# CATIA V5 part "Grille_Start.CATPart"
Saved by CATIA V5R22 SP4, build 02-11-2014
Part number: Grille
Bounding box of the stored display mesh (mm): x 0 to 0, y -310 to 310, z 0 to 410
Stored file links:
  C:\DATA\Car_ASSY\教育モデル\4_SUR\Grille_Start.CATPart
  C:\DATA\Car_ASSY\教育モデル\4_SUR\Grille_FIN.CATPart
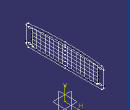
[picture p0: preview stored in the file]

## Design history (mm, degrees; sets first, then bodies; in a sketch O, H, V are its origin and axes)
Set1 "Boss_Danmen"
  Sketch1 on Plane1, origin (-185, 0, 0), H (0, 1, 0), V (0, 0, 1)
    circle A1 centre (-280, 370) radius 6
    circle A2 centre (-280, 260) radius 6
    circle A3 centre (280, 370) radius 6
    circle A4 centre (280, 260) radius 6
    circle A5 centre (-280, 370) radius 9
    point P1 (-280, 370)
    circle A6 centre (-280, 260) radius 9
    point P2 (-280, 260)
    circle A7 centre (280, 260) radius 9
    point P3 (280, 260)
    circle A8 centre (280, 370) radius 9
    point P4 (280, 370)
    radius A5 = 9
    radius A6 = 9
    radius A7 = 9
    radius A8 = 9
    distance P4 V = 280
    distance H P4 = 370
    radius A3 = 6
    distance P3 P4 = 110
    distance V P3 = 280
    radius A4 = 6
    radius A2 = 6
    radius A1 = 6
    distance P1 V = 280
    distance P2 V = 280
    distance H P2 = 260
    distance P2 P1 = 110
    concentricity: P1 A1, P2 A2, P3 A4, P4 A3
  Plane1: type Offset, RefPlane yz-plane, Offset -185
Body1 (main body)
Body2
  Sketch2 on yz-plane, origin (0, 0, 0), H (0, 1, 0), V (0, 0, 1)
    point P1 (0.0002, 410)
    construction line L1 (0.0002, 410) -> (310, 410)
    point P2 (310, 410)
    line L2 (310, 372.6426) -> (310, 250)
    point P3 (310, 230)
    line L3 (290, 230) -> (0, 230)
    point P4 (0, 230)
    circle A1 centre (280, 370) radius 8
    circle A2 centre (280, 260) radius 8
    spline S1 through (0.0002, 410) (184.2802, 403.8794) (310, 390)
    arc A3 centre (290, 250) radius 20 from (290, 230) to (310, 250) ccw
    point P5 (290, 230)
    point P6 (310, 250)
    arc A4 centre (290, 372.6426) radius 20 from (292.7155, 392.4574) to (310, 372.6426) cw
    point P8 (292.7155, 392.4574)
    point P9 (310, 372.6426)
    offsetcurve C1
    point P11 (0.0002, 390)
    point P12 (290.0001, 372.6425)
    construction line L4 (0.0002, 410) -> (0.0002, 390)
    point P13 (0.0002, 410)
    construction line L5 through (0.0002, 410) direction (-1, 0)
    construction line L6 (292.7155, 392.4574) -> (290.0001, 372.6425)
    construction line L7 through (292.7155, 392.4574) direction (0.9907, -0.1358)
    line L8 (260, 376.4843) -> (260, 255)
    point P14 (257.373, 372.6426)
    point P15 (257.373, 250)
    construction line L9 (310, 372.6426) -> (257.373, 372.6426)
    construction line L10 (310, 250) -> (257.373, 250)
    line L11 (255, 250) -> (0, 250)
    point P16 (290, 250)
    point P17 (0, 250)
    construction line L12 (290, 230) -> (290, 250)
    construction line L13 (0, 230) -> (0, 250)
    point P18 (260, 376.4843)
    point P19 (260, 250)
    line L14 (272, 370) -> (260, 370)
    point P20 (272, 370)
    point P21 (260, 370)
    line L15 (288, 370) -> (310, 370)
    point P22 (288, 370)
    point P23 (310, 370)
    line L16 (288, 260) -> (310, 260)
    point P24 (288, 260)
    point P25 (310, 260)
    line L17 (272, 260) -> (260, 260)
    point P26 (272, 260)
    point P27 (260, 260)
    line L18 (260, 275) -> (0, 275)
    point P28 (260, 275)
    point P29 (0, 275)
    construction line L19 (260, 250) -> (260, 275)
    construction line L20 (0, 250) -> (0, 275)
    line L21 (260, 300) -> (0, 300)
    point P30 (260, 300)
    point P31 (0, 300)
    construction line L22 (260, 275) -> (260, 300)
    construction line L23 (0, 275) -> (0, 300)
    line L24 (260, 325) -> (0, 325)
    point P32 (260, 325)
    point P33 (0, 325)
    construction line L25 (260, 300) -> (260, 325)
    construction line L26 (0, 300) -> (0, 325)
    line L27 (260, 350) -> (0, 350)
    point P34 (260, 350)
    point P35 (0, 350)
    construction line L28 (260, 325) -> (260, 350)
    construction line L29 (0, 325) -> (0, 350)
    line L30 (260, 375) -> (0, 375)
    point P36 (260, 375)
    point P37 (0, 375)
    construction line L31 (260, 350) -> (260, 375)
    construction line L32 (0, 350) -> (0, 375)
    arc A5 centre (255, 255) radius 5 from (260, 255) to (255, 250) cw
    point P38 (260, 255)
    point P39 (255, 250)
    line L33 (17.5, 250) -> (17.5, 389.9532)
    point P41 (17.5, 250)
    point P42 (17.5, 389.9532)
    line L34 (52.5, 250) -> (52.5, 389.5709)
    point P43 (52.5, 250)
    point P44 (52.5, 389.5709)
    line L35 (87.5, 250) -> (87.5, 388.769)
    point P45 (87.5, 250)
    point P46 (87.5, 388.769)
    line L36 (122.5, 250) -> (122.5, 387.4859)
    point P47 (122.5, 250)
    point P48 (122.5, 387.4859)
    line L37 (157.5, 250) -> (157.5, 385.6484)
    point P49 (157.5, 250)
    point P50 (157.5, 385.6484)
    line L38 (192.5, 250) -> (192.5, 383.1854)
    point P51 (192.5, 250)
    point P52 (192.5, 383.1854)
    line L39 (227.5, 250) -> (227.5, 380.0419)
    point P53 (227.5, 250)
    point P54 (227.5, 380.0419)
    point P55 (-0.0002, 410)
    point P56 (-310, 410)
    construction line L40 (-0.0002, 410) -> (-310, 410)
    point P57 (-310, 230)
    point P58 (0, 230)
    point P59 (-290, 230)
    point P60 (-310, 250)
    point P62 (-292.7155, 392.4574)
    point P63 (-310, 372.6426)
    point P65 (-0.0002, 390)
    point P66 (-290.0001, 372.6425)
    point P67 (-257.373, 372.6426)
    point P68 (-257.373, 250)
    point P69 (-290, 250)
    point P70 (0, 250)
    point P71 (-260, 376.4843)
    point P72 (-260, 250)
    point P73 (-272, 370)
    point P74 (-260, 370)
    point P75 (-288, 370)
    point P76 (-310, 370)
    point P77 (-288, 260)
    point P78 (-310, 260)
    point P79 (-272, 260)
    point P80 (-260, 260)
    point P81 (-260, 275)
    point P82 (0, 275)
    point P83 (-260, 300)
    point P84 (0, 300)
    point P85 (-260, 325)
    point P86 (0, 325)
    point P87 (-260, 350)
    point P88 (0, 350)
    point P89 (-260, 375)
    point P90 (0, 375)
    point P91 (-260, 255)
    point P92 (-255, 250)
    point P94 (-17.5, 250)
    point P95 (-17.5, 389.9532)
    point P96 (-52.5, 250)
    point P97 (-52.5, 389.5709)
    point P98 (-87.5, 250)
    point P99 (-87.5, 388.769)
    point P100 (-122.5, 250)
    point P101 (-122.5, 387.4859)
    point P102 (-157.5, 250)
    point P103 (-157.5, 385.6484)
    point P104 (-192.5, 250)
    point P105 (-192.5, 383.1854)
    point P106 (-227.5, 250)
    point P107 (-227.5, 380.0419)
    line L41 (-310, 372.6426) -> (-310, 250)
    line L42 (-290, 230) -> (0, 230)
    circle A6 centre (-280, 370) radius 8
    circle A7 centre (-280, 260) radius 8
    spline S2 through (-0.0002, 410) (-184.2802, 403.8794) (-310, 390)
    arc A8 centre (-290, 250) radius 20 from (-290, 230) to (-310, 250) cw
    arc A9 centre (-290, 372.6426) radius 20 from (-292.7155, 392.4574) to (-310, 372.6426) ccw
    offsetcurve C2
    line L43 (-260, 376.4843) -> (-260, 255)
    line L44 (-255, 250) -> (0, 250)
    line L45 (-272, 370) -> (-260, 370)
    line L46 (-288, 370) -> (-310, 370)
    line L47 (-288, 260) -> (-310, 260)
    line L48 (-272, 260) -> (-260, 260)
    line L49 (-260, 275) -> (0, 275)
    line L50 (-260, 300) -> (0, 300)
    line L51 (-260, 325) -> (0, 325)
    line L52 (-260, 350) -> (0, 350)
    line L53 (-260, 375) -> (0, 375)
    arc A10 centre (-255, 255) radius 5 from (-260, 255) to (-255, 250) ccw
    line L54 (-17.5, 250) -> (-17.5, 389.9532)
    line L55 (-52.5, 250) -> (-52.5, 389.5709)
    line L56 (-87.5, 250) -> (-87.5, 388.769)
    line L57 (-122.5, 250) -> (-122.5, 387.4859)
    line L58 (-157.5, 250) -> (-157.5, 385.6484)
    line L59 (-192.5, 250) -> (-192.5, 383.1854)
    line L60 (-227.5, 250) -> (-227.5, 380.0419)
    point P108 (0.0002, 410)
    point P109 (310, 390)
    point P110 (184.2802, 403.8794)
    point P111 (-0.0002, 410)
    point P112 (-310, 390)
    point P113 (-184.2802, 403.8794)
    distance H L3 = 230
    distance L2 V = 310
    distance P109 L1 = 20
    distance P2 P3 = 180
    distance V P110 = 184.2802
    distance P110 P109 V = 13.8794
    distance P108 P4 = 180
    radius A3 = 20
    radius A4 = 20
    distance L2 L8 = 50
    distance L3 L11 = 20
    distance L16 L3 = 30
    distance L15 L16 = 110
    distance A1 L15 = 8
    distance A1 L15 = 8
    distance A1 L2 = 38
    distance A2 L16 = 8
    distance A2 L16 = 8
    distance L2 A2 = 38
    distance L11 L18 = 25
    distance L18 L21 = 25
    distance L21 L24 = 25
    distance L24 L27 = 25
    distance L27 L30 = 25
    radius A5 = 5
    distance V L33 = 17.5
    distance L33 L34 = 35
    distance L34 L35 = 35
    distance L35 L36 = 35
    distance L36 L37 = 35
    distance L37 L38 = 35
    distance L38 L39 = 35
    horizontal: L1 H, L3 H, L14 H, L15 H, L16 H, L17 H
    vertical: L2 V, L33 V, L34 V, L35 V, L36 V, L37 V, L38 V, L39 V
    coincidence: P4 V, P108 P1, P109 L2, P2 L2, L3 P3, L2 P3, P108 P13, P12 C1, P16 L11, P20 A1, P21 L8, P22 L14, P22 A1, P23 L2, P24 A2, P25 L2, P26 L16, P26 A2, P27 L8, L8 P19, L11 P19, P41 L11, P42 C1, P43 L11, P44 C1, P45 L11, P46 C1, P47 L11, P48 C1, P49 L11, P50 C1, P51 L11, P52 C1, P53 L11, P54 C1, P4 P58, P17 P70, P29 P82, P31 P84, P33 P86, P35 P88, P37 P90
    tangency: A3 L3, A3 L2, A4 S1, A4 L2, L5 S1, L7 S1, A5 L8, A5 L11
    perpendicularity: L4 L5, L6 L7, L9 L2, L9 L8, L10 L2, L10 L8, L12 L3, L12 L11, L13 L3, L13 L11, L19 L11, L19 L18, L20 L11, L20 L18, L22 L18, L22 L21, L23 L18, L23 L21, L25 L21, L25 L24, L26 L21, L26 L24, L28 L24, L28 L27, L29 L24, L29 L27, L31 L27, L31 L30, L32 L27, L32 L30
    symmetry: P1 P55 V, P2 P56 V, L1 L40 V, P3 P57 V, P4 P58 V, P5 P59 V, P6 P60 V, P8 P62 V, P9 P63 V, P11 P65 V, P12 P66 V, P14 P67 V, P15 P68 V, P16 P69 V, P17 P70 V, P18 P71 V, P19 P72 V, P20 P73 V, P21 P74 V, P22 P75 V, P23 P76 V, P24 P77 V, P25 P78 V, P26 P79 V, P27 P80 V, P28 P81 V, P29 P82 V, P30 P83 V, P31 P84 V, P32 P85 V, P33 P86 V, P34 P87 V, P35 P88 V, P36 P89 V, P37 P90 V, P38 P91 V, P39 P92 V, P41 P94 V, P42 P95 V, P43 P96 V, P44 P97 V, P45 P98 V, P46 P99 V, P47 P100 V, P48 P101 V, P49 P102 V, P50 P103 V, P51 P104 V, P52 P105 V, P53 P106 V, P54 P107 V, L2 L41 V, L3 L42 V, A1 A6 V, A2 A7 V, S1 S2 V, A3 A8 V, A4 A9 V, C1 C2 V, L8 L43 V, L11 L44 V, L14 L45 V, L15 L46 V, L16 L47 V, L17 L48 V, L18 L49 V, L21 L50 V, L24 L51 V, L27 L52 V, L30 L53 V, A5 A10 V, L33 L54 V, L34 L55 V, L35 L56 V, L36 L57 V, L37 L58 V, L38 L59 V, L39 L60 V, P108 P111 V, P109 P112 V, P110 P113 V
